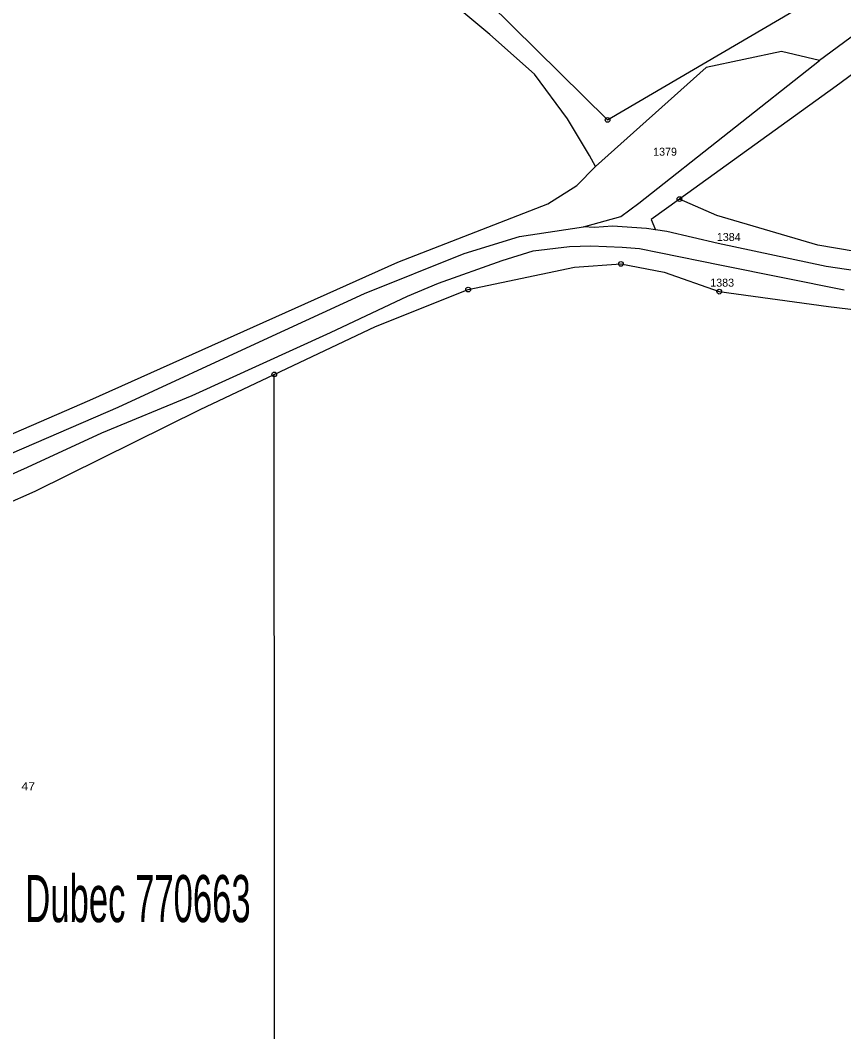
# Model space of a CAD drawing. Extents: x -872229 to -869198, y -1075981 to -1074329.
# Drawn here: x -870664.3 to -870489.5, y -1075151.2 to -1074936.4 of the extents above; entities that cross this region are included whole.
import ezdxf
from ezdxf.enums import TextEntityAlignment as Align

# ---------------------------------------------------------------- set-up
doc = ezdxf.new("R2010")
doc.units = 0
doc.header["$LTSCALE"] = 0.68
for name, color, linetype, lineweight in [('1', 7, 'Continuous', 25), ('7', 7, 'Continuous', 13), ('8', 7, 'Continuous', 25)]:
    doc.layers.add(name, color=color, linetype=linetype, lineweight=lineweight)
doc.layers.add('2', color=7, linetype='Continuous')

msp = doc.modelspace()

# ---------------------------------------------------------------- linework, layer by layer
at = {"layer": '1'}
for points in [[(-870352.08, -1074839.16), (-870370.51, -1074852.86), (-870398.03, -1074874.22), (-870412.45, -1074885.65), (-870420.69, -1074894.67), (-870447.23, -1074917.28), (-870451.03, -1074920.77), (-870491.11, -1074950.4), (-870524.35, -1074974.36)], [(-870605.12, -1074892.84), (-870539.63, -1074957.56), (-870491.54, -1074929.27), (-870432.98, -1074889.01), (-870388.3, -1074858.96)], [(-870388.3, -1074858.96), (-870401.56, -1074868.78), (-870415.98, -1074880.21), (-870424.22, -1074889.23), (-870450.76, -1074911.84), (-870454.56, -1074915.33), (-870494.64, -1074944.96)], [(-870542.19, -1074967.42), (-870543.47, -1074965.12), (-870548.12, -1074957.33), (-870555.12, -1074947.81), (-870564.62, -1074939.42), (-870592.11, -1074916.44), (-870602.17, -1074909.34), (-870607.46, -1074906.7), (-870613.94, -1074902.37)], [(-870494.64, -1074944.96), (-870502.7, -1074943), (-870518.69, -1074946.39), (-870542.19, -1074967.42)], [(-870544.73, -1074980.25), (-870536.82, -1074978.04), (-870533, -1074975.21), (-870494.64, -1074944.96)], [(-870723.96, -1075050), (-870693.71, -1075036.28), (-870649.55, -1075017.06), (-870584.14, -1074987.8), (-870552.32, -1074975.37), (-870546.15, -1074971.5), (-870542.19, -1074967.42)], [(-870524.35, -1074974.36), (-870530.38, -1074978.71), (-870529.43, -1074980.92)], [(-870115.36, -1074981.96), (-870117.37, -1074995.15), (-870140.21, -1074996.52), (-870172.56, -1075001.14), (-870203.84, -1075002.96), (-870227.79, -1075005.61), (-870254.49, -1075003.89), (-870314.81, -1075000.31), (-870361.75, -1074998.26), (-870391.78, -1074996.03), (-870411.2, -1074993.72), (-870422.25, -1074993.21), (-870453.27, -1074990.57), (-870470.34, -1074988.35), (-870494.98, -1074984.19), (-870516.43, -1074977.89), (-870524.35, -1074974.36)], [(-870760.55, -1075074.8), (-870736.8, -1075061.65), (-870716.28, -1075051.57), (-870684.01, -1075036.04), (-870643.52, -1075018.55), (-870612.61, -1075004.24), (-870591.23, -1074994.43), (-870570.04, -1074985.9), (-870558.3, -1074982.28), (-870544.73, -1074980.25)], [(-870529.43, -1074980.92), (-870531.32, -1074980.63), (-870538.56, -1074980.13), (-870542.37, -1074980.4), (-870544.73, -1074980.25)], [(-870471.11, -1074991.94), (-870493.23, -1074988.69), (-870516.16, -1074983.81), (-870527.05, -1074981.27), (-870529.43, -1074980.92)], [(-870746.19, -1075071.27), (-870732.98, -1075064.74), (-870715.15, -1075055.28), (-870702.93, -1075049.25), (-870662.75, -1075031.31), (-870646.95, -1075024.02), (-870627.8, -1075016.08), (-870598.46, -1075002.7), (-870582.08, -1074994.97), (-870575.53, -1074992.25), (-870561.97, -1074987.44), (-870555.39, -1074985.35), (-870547.72, -1074984.42), (-870543.16, -1074984.27), (-870536.54, -1074984.58), (-870532.83, -1074984.88), (-870528.68, -1074985.73), (-870515.43, -1074988.43), (-870489.43, -1074993.61)], [(-870610.36, -1075011.6), (-870588.87, -1075001.44), (-870569.21, -1074993.58), (-870546.64, -1074988.8), (-870536.79, -1074988.15), (-870527.6, -1074989.88), (-870515.91, -1074994.03), (-870492.69, -1074997.19), (-870452.83, -1075001.97), (-870413.18, -1075005.54), (-870363.54, -1075007.87), (-870304.97, -1075011.83), (-870245.64, -1075015.91), (-870217.62, -1075016.65), (-870207.57, -1075016.13)], [(-870746.19, -1075071.27), (-870740.01, -1075073.65), (-870701.56, -1075054.27), (-870661.14, -1075036.37), (-870626.13, -1075019.06), (-870610.36, -1075011.6)], [(-870610.3, -1075233.15), (-870610.33, -1075122.57), (-870610.36, -1075011.6)]]:
    msp.add_lwpolyline(points, dxfattribs=at)
at = {"layer": '8'}
for centre, radius in [((-870539.63, -1074957.5599), 0.5), ((-870539.63, -1074957.5599), 0.0303), ((-870524.35, -1074974.3599), 0.5), ((-870524.35, -1074974.3599), 0.0303), ((-870536.79, -1074988.1499), 0.5), ((-870536.79, -1074988.1499), 0.0303), ((-870569.21, -1074993.5799), 0.5), ((-870569.21, -1074993.5799), 0.0303), ((-870515.91, -1074994.0299), 0.5), ((-870515.91, -1074994.0299), 0.0303), ((-870610.36, -1075011.5999), 0.5), ((-870610.36, -1075011.5999), 0.0303)]:
    msp.add_circle(centre, radius, dxfattribs=at)

# ---------------------------------------------------------------- texts
at = {"layer": '2'}
for s, p in [('1379', (-870529.95, -1074965.16)), ('1384', (-870516.42, -1074983.27)), ('1383', (-870517.82, -1074992.97))]:
    msp.add_text(s, height=1.7, dxfattribs=at).set_placement(p)
at = {"layer": '2', "width": 1.15}
msp.add_text('47', height=1.7, dxfattribs=at).set_placement((-870662.59, -1075099.91), align=Align.CENTER)
at = {"layer": '7', "width": 0.55}
msp.add_text('Dubec 770663', height=10, dxfattribs=at).set_placement((-870639.3, -1075127.927), align=Align.CENTER)

doc.saveas('drawing.dxf')
